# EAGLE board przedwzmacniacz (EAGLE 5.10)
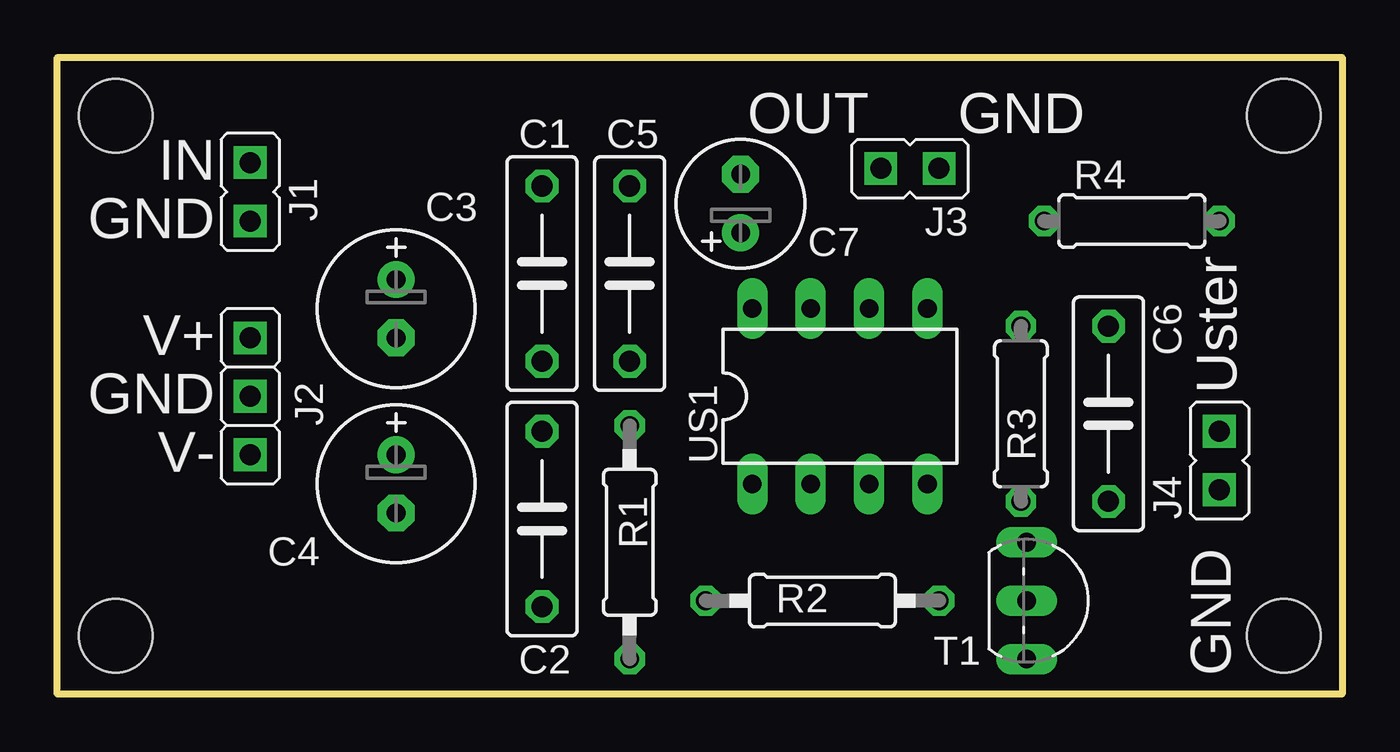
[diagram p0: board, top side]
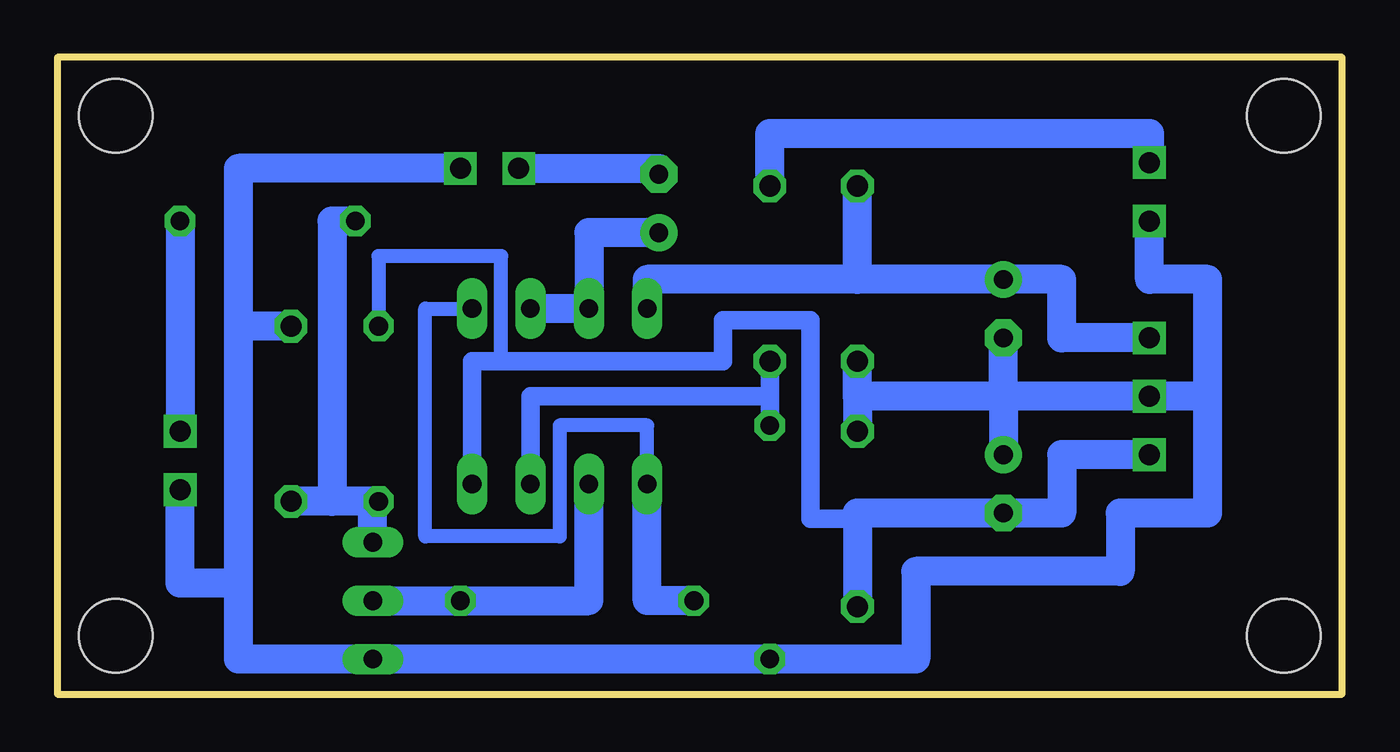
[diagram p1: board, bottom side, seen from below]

Size 55.88 x 27.69 mm. Coordinates in mm from the lower left corner, seen from the top.
Outline: 0,27.69 55.88,27.69 55.88,0 0,0 0,27.69
Copper layers (1*16): Top 0.035mm / dielectric 1.5mm / Bottom 0.035mm
Design rules "default": minimum track width 10mil, minimum drill 24mil, track to track 8mil, track to pad 8mil, pad to pad 8mil, via to via 8mil, smd to smd 8mil, copper to edge 40mil, drill to drill 8mil, minimum pad ring 10mil, minimum via ring 8mil, stop-mask expansion 4mil, vias tented up to drill 0mil, thermal gap 10mil
Holes 3.2 mm at 2.54,25.15 2.54,2.54 53.34,25.15 53.34,2.54

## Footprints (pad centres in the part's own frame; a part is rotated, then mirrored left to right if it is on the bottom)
C075-032X103 = drill 0.914 octagon: 1 -3.81,0; 2 3.81,0
E2,5-7 = drill 0.813 pad 1.6 round: + -1.27,0 | drill 0.813 pad 1.6 octagon: - 1.27,0
E2,5-6 = drill 0.813 pad 1.6 round: + -1.27,0 | drill 0.813 pad 1.6 octagon: - 1.27,0
JP1 = drill 0.914 pad 1.422 square: 1 0,-1.27; 2 0,1.27
0207/10 = drill 0.813 octagon: 1 -5.08,0; 2 5.08,0
0207/7 = drill 0.813 octagon: 1 -3.81,0; 2 3.81,0
TO92-BCE = drill 0.813 long: B -2.54,0; C 0,0; E 2.54,0
DIL08 = drill 0.813 long: 1 -3.81,-3.81; 2 -1.27,-3.81; 3 1.27,-3.81; 4 3.81,-3.81; 5 3.81,3.81; 6 1.27,3.81; 7 -1.27,3.81; 8 -3.81,3.81

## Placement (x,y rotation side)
C1  [C075-032X103]  21.08,18.29 270 top
C2  [C075-032X103]  21.08,7.62 270 top
C3  [E2,5-7]  14.73,16.76 270 top
C4  [E2,5-7]  14.73,9.14 270 top
C5  [C075-032X103]  24.89,18.29 270 top
C6  [C075-032X103]  45.72,12.19 270 top
C7  [E2,5-6]  29.72,21.34 90 top
E$13  [JP1]  8.38,11.68 0 top
J1  [JP1]  8.38,21.84 0 top
J2  [JP1]  8.38,14.22 0 top
J3  [JP1]  37.08,22.86 90 top
J4  [JP1]  50.55,10.16 0 top
R1  [0207/10]  24.89,6.6 270 top
R2  [0207/10]  33.27,4.06 0 top
R3  [0207/7]  41.91,12.19 90 top
R4  [0207/7]  46.74,20.57 0 top
T1  [TO92-BCE]  42.16,4.06 270 top
US1  [DIL08]  34.04,12.95 0 top

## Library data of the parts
C1-C7 R1-R4 = rcl
E$13 J1-J4 = hybrid
T1 = transistor
US1 = 40xx

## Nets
S$1: C5.1 J1.2
S$2: C5.2 R1.1
S$3: J4.2 R4.2
S$4: C2.2 E$13.1 R3.2 US1.4
S$5: C1.1 J2.2 US1.8
S$6: C7.+ US1.6 US1.7
S$7: C6.2 R4.1 T1.B
S$8: R2.1 US1.1 US1.5
S$9: C7.- J3.2
S$10: R2.2 T1.C
S$11: C1.2 C2.1 C3.- C6.1 J1.1 J2.1 J3.1 J4.1 R1.2

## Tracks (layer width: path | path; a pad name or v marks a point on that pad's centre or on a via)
S$1
  Bottom 1.27: C5.1 24.89,24.38 8.38,24.38 J1.2
S$2
  Bottom 0.813: 35.31,8.89 35.31,12.95 24.89,12.95 | R1.1 24.89,12.95 | 24.89,12.95 C5.2
S$3
  Bottom 1.27: R4.2 J4.2
S$4
  Bottom 0.61: 36.58,14.48 36.58,19.05 41.91,19.05 R3.2
  Bottom 0.813: 21.08,7.62 23.11,7.62 23.11,16.26 26.92,16.26 26.92,14.48 36.58,14.48 37.85,14.48 US1.4
  Bottom 1.27: C2.2 21.08,7.62 21.08,7.87 12.19,7.87 12.19,10.41 E$13.1
S$5
  Bottom 1.27: US1.8 30.23,18.03 21.08,18.03 | 21.08,18.03 C1.1 | 21.08,18.03 12.19,18.03 12.19,15.49 J2.2
S$6
  Bottom 1.27: US1.6 US1.7 32.77,20.07 C7.+
S$7
  Bottom 1.27: 43.94,8.38 42.16,8.38 T1.B | 43.94,8.38 C6.2 | R4.1 43.94,20.57 43.94,8.38
S$8
  Bottom 0.61: US1.1 30.23,11.68 34.04,11.68 34.04,6.86 39.88,6.86 39.88,16.76 US1.5
  Bottom 1.27: R2.1 30.23,4.06 US1.1
S$9
  Bottom 1.27: J3.2 29.72,22.86 C7.-
S$10
  Bottom 1.27: 32.77,8.89 32.77,4.06 R2.2 T1.C
S$11
  Bottom 1.27: J4.1 50.55,4.83 48.01,4.83 | 48.01,4.83 48.01,16 | 48.01,16 48.01,22.86 J3.1 | 48.01,4.83 48.01,1.52 R1.2 18.54,1.52 18.54,5.33 9.65,5.33 9.65,7.87 5.84,7.87 5.84,12.95 | 21.08,12.95 C1.2 | 21.08,12.95 C2.1 | J1.1 8.38,18.03 5.84,18.03 5.84,12.95 | 14.73,12.95 C3.- | 14.73,12.95 21.08,12.95 | 14.73,12.95 14.73,10.41 | 14.73,12.95 J2.1 5.84,12.95 | C6.1 48.01,16

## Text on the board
tNames: OUT | GND | IN | GND | Uster | V+ | GND | V- | GND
